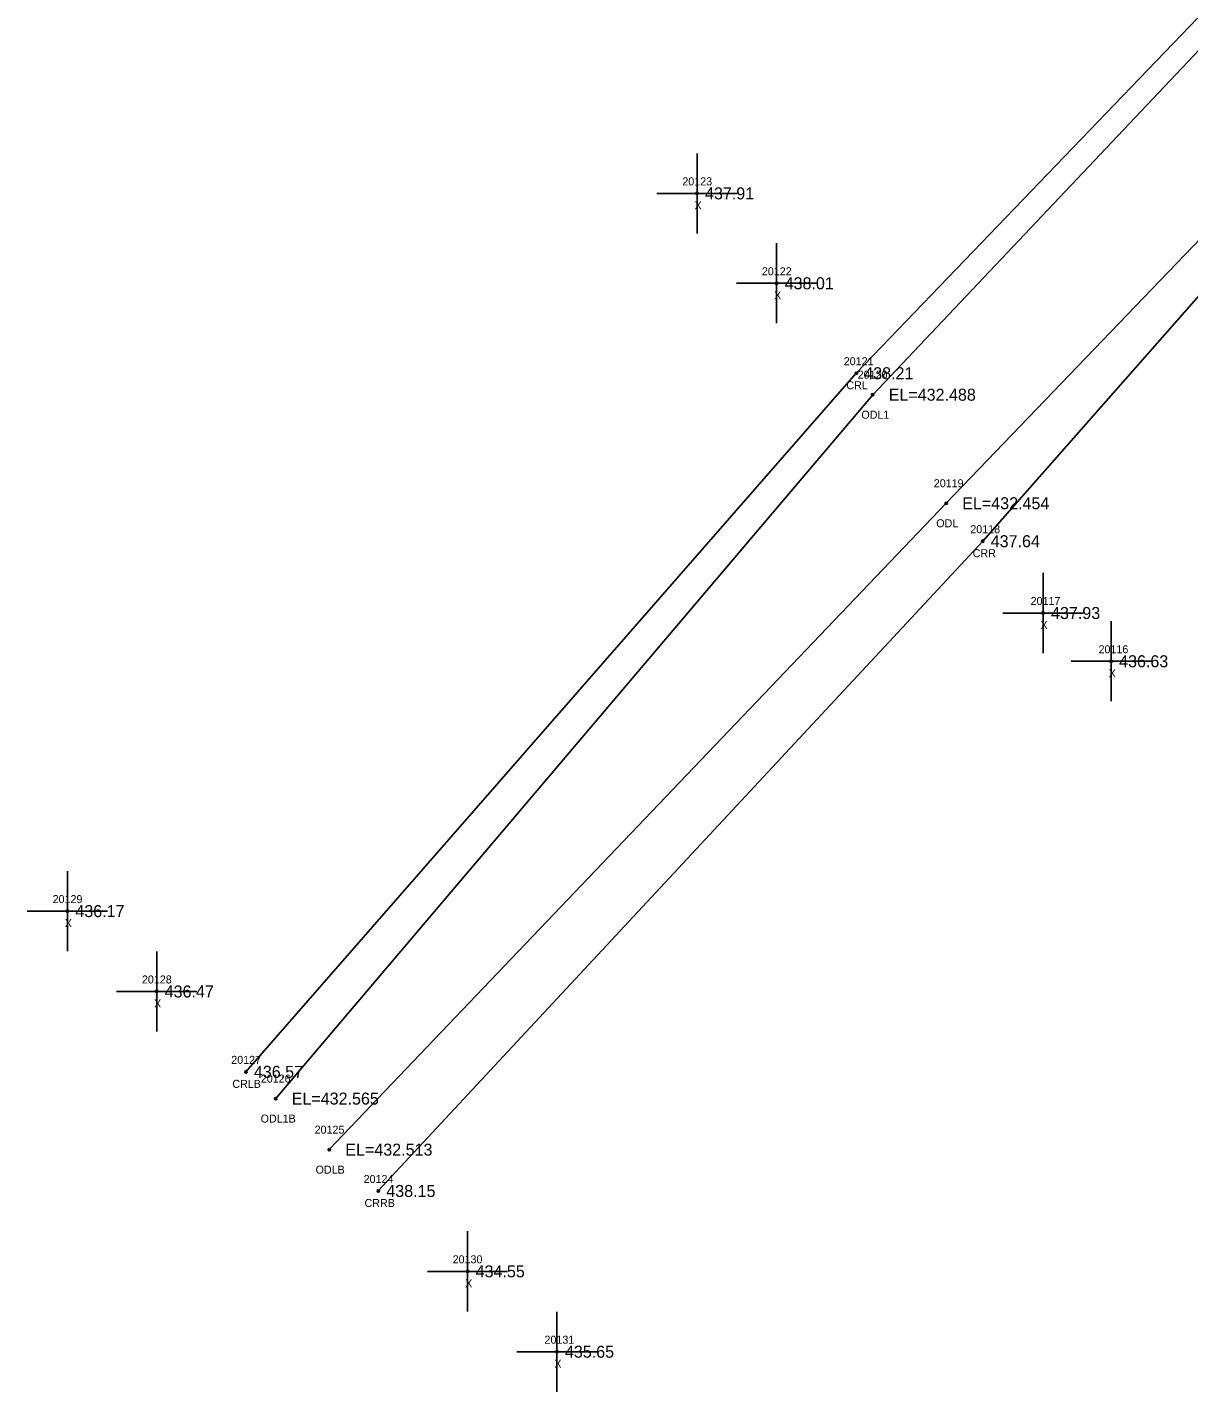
# Model space of a CAD drawing. Extents: x 1810114 to 1811498, y 790790 to 791824.
# Drawn here: x 1810517.6 to 1810662.6, y 790789.8 to 790960.3 of the extents above; entities that cross this region are included whole.
import ezdxf

# ---------------------------------------------------------------- set-up
doc = ezdxf.new("R2010")
doc.units = 0
for name, color, linetype in [('RD_EX_H2O', 7, 'Continuous'), ('RD_EX_H2O_txCode', 7, 'Continuous'), ('RD_EX_Misc', 7, 'Continuous'), ('RD_EX_Misc_txCode', 7, 'Continuous'), ('RD_EX_TX_H2O_ELEV', 7, 'Continuous'), ('RD_EX_TX_Misc_ELEV', 7, 'Continuous'), ('RD_SMD_Locator', 7, 'Continuous')]:
    doc.layers.add(name, color=color, linetype=linetype)

msp = doc.modelspace()

# ---------------------------------------------------------------- linework, layer by layer
at = {"layer": 'RD_EX_H2O'}
for points in [[(1810767.47, 791275.24), (1810763.99, 791268.4), (1810740.03, 791179.13), (1810709.69, 791074.11), (1810683.47, 790982.07), (1810621.06, 790917.07), (1810544.86, 790829.8)], [(1810771.9, 791274.91), (1810769.68, 791267.55), (1810744.28, 791178.39), (1810714.79, 791074.77), (1810686.49, 790981.43), (1810623.11, 790914.39), (1810548.58, 790826.46)], [(1810781.26, 791266.77), (1810779.82, 791257.8), (1810759.51, 791170.68), (1810730.33, 791070.87), (1810714.55, 790997.81), (1810711.23, 790989.07), (1810703.16, 790974.66), (1810632.29, 790900.83), (1810555.27, 790820.08)], [(1810709.99, 790982.91), (1810705.03, 790973.57), (1810636.85, 790896.09), (1810561.39, 790814.92)]]:
    msp.add_lwpolyline(points, dxfattribs=at)
at = {"layer": 'RD_EX_Misc'}
for p, q in [((1810601.18, 790934.54), (1810601.18, 790944.54)), ((1810596.18, 790939.54), (1810606.18, 790939.54)), ((1810611.12, 790923.31), (1810611.12, 790933.31)), ((1810606.12, 790928.31), (1810616.12, 790928.31)), ((1810644.38, 790882.12), (1810644.38, 790892.12)), ((1810639.38, 790887.12), (1810649.38, 790887.12)), ((1810652.88, 790876.09), (1810652.88, 790886.09)), ((1810647.88, 790881.09), (1810657.88, 790881.09)), ((1810522.57, 790844.88), (1810522.57, 790854.88)), ((1810517.57, 790849.88), (1810527.57, 790849.88)), ((1810533.72, 790834.84), (1810533.72, 790844.84)), ((1810528.72, 790839.84), (1810538.72, 790839.84)), ((1810572.54, 790799.88), (1810572.54, 790809.88)), ((1810567.54, 790804.88), (1810577.54, 790804.88)), ((1810583.69, 790789.84), (1810583.69, 790799.84)), ((1810578.69, 790794.84), (1810588.69, 790794.84))]:
    msp.add_line(p, q, dxfattribs=at)
at = {"layer": 'RD_SMD_Locator'}
for centre in [(1810601.18, 790939.54), (1810611.12, 790928.31), (1810621.06, 790917.07), (1810623.11, 790914.39), (1810632.29, 790900.83), (1810636.85, 790896.09), (1810644.38, 790887.12), (1810652.88, 790881.09), (1810522.57, 790849.88), (1810533.72, 790839.84), (1810544.86, 790829.8), (1810548.58, 790826.46), (1810555.27, 790820.08), (1810561.39, 790814.92), (1810572.54, 790804.88), (1810583.69, 790794.84)]:
    msp.add_circle(centre, 0.15, dxfattribs=at)

# ---------------------------------------------------------------- texts
at = {"layer": 'RD_EX_H2O_txCode'}
for s, p in [('20121', (1810619.5, 790918.07)), ('20120', (1810621.24, 790916.39)), ('CRL', (1810619.83, 790915.07)), ('ODL1', (1810621.7, 790911.39)), ('20119', (1810630.74, 790902.83)), ('ODL', (1810631.05, 790897.83)), ('20118', (1810635.3, 790897.09)), ('CRR', (1810635.6, 790894.09)), ('20127', (1810543.03, 790830.8)), ('20126', (1810546.72, 790828.46)), ('CRLB', (1810543.16, 790827.8)), ('ODL1B', (1810546.7, 790823.46)), ('20125', (1810553.44, 790822.08)), ('ODLB', (1810553.56, 790817.08)), ('20124', (1810559.56, 790815.92)), ('CRRB', (1810559.67, 790812.92))]:
    msp.add_text(s, height=1, dxfattribs=at).set_placement(p)
at = {"layer": 'RD_EX_Misc_txCode'}
for s, p in [('20123', (1810599.35, 790940.54)), ('X', (1810600.87, 790937.54)), ('20122', (1810609.28, 790929.31)), ('X', (1810610.8, 790926.31)), ('20117', (1810642.83, 790888.12)), ('X', (1810644.06, 790885.12)), ('20116', (1810651.31, 790882.09)), ('X', (1810652.57, 790879.09)), ('20129', (1810520.73, 790850.88)), ('X', (1810522.25, 790847.88)), ('20128', (1810531.88, 790840.84)), ('X', (1810533.4, 790837.84)), ('20130', (1810570.67, 790805.88)), ('X', (1810572.23, 790802.88)), ('20131', (1810582.14, 790795.84)), ('X', (1810583.37, 790792.84))]:
    msp.add_text(s, height=1, dxfattribs=at).set_placement(p)
at = {"layer": 'RD_EX_TX_H2O_ELEV'}
for s, p in [('438.21', (1810622.06, 790916.32)), ('EL=432.488', (1810625.11, 790913.64)), ('EL=432.454', (1810634.29, 790900.08)), ('437.64', (1810637.85, 790895.34)), ('436.57', (1810545.86, 790829.05)), ('EL=432.565', (1810550.58, 790825.71)), ('EL=432.513', (1810557.27, 790819.33)), ('438.15', (1810562.39, 790814.17))]:
    msp.add_text(s, height=1.5, dxfattribs=at).set_placement(p)
at = {"layer": 'RD_EX_TX_Misc_ELEV'}
for s, p in [('437.91', (1810602.18, 790938.79)), ('438.01', (1810612.12, 790927.56)), ('437.93', (1810645.38, 790886.37)), ('436.63', (1810653.88, 790880.34)), ('436.17', (1810523.57, 790849.13)), ('436.47', (1810534.72, 790839.09)), ('434.55', (1810573.54, 790804.13)), ('435.65', (1810584.69, 790794.09))]:
    msp.add_text(s, height=1.5, dxfattribs=at).set_placement(p)

doc.saveas('drawing.dxf')
